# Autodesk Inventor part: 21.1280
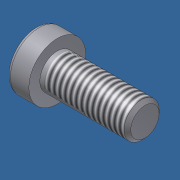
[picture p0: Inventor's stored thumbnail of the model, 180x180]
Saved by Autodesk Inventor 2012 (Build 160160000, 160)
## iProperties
Created: 2006-02
Part Number: 21.1280
Material: Steel, Mild
Description: M8X22 SHCS
Document SubType Name: Modeling
Standard: DIN 7984
Designer: Andy Moles
Standards Organization: DIN
Language: en-US
Size Designation: M8 x 20
Categories: <MemberInstance><Categories><Category DisplayName="Fasteners" InternalName="e4da775c-781d-43d5-af7c-5136215cf5a6" Mnemonic="FSTN"><Category DisplayName="Bolts"
Density: 7.86 g/cm^3
Mass: 13.0532 g
Surface Area: 10.6794 cm^2
Volume: 1.66071 cm^3
Vendor: S
Author: Andy Moles
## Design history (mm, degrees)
body "Solid1"
workplane "Work Plane1"
revolve "Body" stored, may be unused: angle "d10" = 90 deg
sketch "Sketch2"
  geometry: L1 (0, -7.8)-(0, 10.4) reference; L2 (-7.8, 0)-(10.4, 0) reference; L3 (2.887, 0)-(1.443, -2.5); L4 (1.443, -2.5)-(-1.443, -2.5); L5 (-1.443, -2.5)-(-2.887, 0); L6 (-2.887, 0)-(-1.443, 2.5); L7 (-1.443, 2.5)-(1.443, 2.5); L8 (1.443, 2.5)-(2.887, 0); 2 further points
  constraints: 12 end point, 1 coincident, 1 horizontal alignment, 1 point on line, 12 other
extrude "Slot" join sketch "Sketch2" stored distance "d11" = 10; taper "d12" = 0 deg
fillet "Fillet1" dims "d17" = 0.8 (= RR)
feature "Thread" dims "d13" = 22, "d14" = 0
chamfer "Chamfer1" distance "d15" = 0.76681 (= -0.5 x SPD + 0.5 x GD); stored, may be unused: second distance "d16" = 0.76681 (= GUL), angle "d27" = 45 deg
sketch "Sketch1"
  geometry: L1 (0.467, 0)-(22, 0); L2 (22, 0)-(22, 4); L3 (22, 4)-(1, 4); L4 (1, 4)-(0.233, 4); L5 (0.233, 4)-(0, 4); L6 (0, 4)-(0, 6.5); L7 (0, 6.5)-(-5, 6.5); L8 (-5, 6.5)-(-5, 2.887); L9 (-5, 2.887)-(-1.2, 2.887); L10 (-1.2, 2.887)-(0.467, 0); L11 (-7.5, 0)-(27.5, 0) reference; L12 (0, -0.65)-(0, 8.45) reference; L13 (1, 4)-(0, 4)
  constraints: 22 end point, 6 parallel, 2 collinear, 2 perpendicular, 1 horizontal, 1 point on line
  dimensions: "d1" = 21 distance from line of L3.end L2 (= GEL); "d2" = 0.76691 distance of L4.end L3.end (computed from GAL); "d3" = 5 distance between parallel lines of L8 L6 (= KOH); "d4" = 3.8 distance of L8.end L9.end (= INTI); "d5" = 60 deg angle of L10 L1; "d6" = 8 diameter of L3 L1 (= GD); "d7" = 8 diameter of L5 L1 (= BDM); "d8" = 5.7735 diameter of L9 L1 (= 1.1547 x SW); "d9" = 13 diameter of L7 L1 (= KOD); "d26" = 22 distance between parallel lines of L12 L2 (= NLG)
other parameters: "GD" = 8 (= NND) [user parameter; used in 2 equation terms], "NLG" = 22 [user parameter; used in 1 equation term], "GEL" = 21 [user parameter; used in 1 equation term], "KOD" = 13 [user parameter; used in 1 equation term], "KOH" = 5 [user parameter; used in 1 equation term], "INTI" = 3.8 [user parameter; used in 1 equation term], "GAL" = 0.76681 (= 0.61345 x PTC) [user parameter; used in 1 equation term], "GUL" = 0.76681 (= 0.61345 x PTC) [user parameter; used in 1 equation term], "BDM" = 8 (= NND) [user parameter; used in 1 equation term], "SW" = 5 [user parameter; used in 2 equation terms], "RR" = 0.8 [user parameter; used in 1 equation term], "SPD" = 6.46637 (= NND - 1.2269 x PTC) [user parameter; used in 1 equation term], "d19" = 0, "d28" = 0, "d29" = 0, "TOA" = 30 deg [user parameter], "GD1" = 6.46637 (= THREADDIA - 1.2269 x PTC) [user parameter], "THREADDIA" = 8 [user parameter; used in 1 equation term], "FAWI" = 45 deg [user parameter], "ANG" = 120 deg [user parameter], "TPU" = 8 (computed from PTC) [user parameter], "PTC" = 1.25 [user parameter; used in 5 equation terms], "NND" = 8 [user parameter; used in 3 equation terms], "E0" = 5.775 (= 1.155 x SW) [user parameter]
